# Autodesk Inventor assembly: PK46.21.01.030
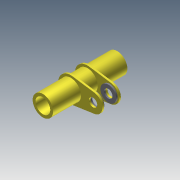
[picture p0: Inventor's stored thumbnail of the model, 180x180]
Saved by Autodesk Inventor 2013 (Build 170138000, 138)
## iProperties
Created: 2005-04
Part Number: PK46.21.01.030
Document SubType Name: Assembly
Designer: salex
Manufacturer: Standard
Standards Organization: Custom
Author: salex
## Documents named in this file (4)
- C:\Product Design Suite 2013\Data\Assy, Chassis, Front\PK46.21.01.030.iam
- C:\Product Design Suite 2013\Data\Assy, Chassis, Front\PK46.21.01.006.ipt
- C:\Product Design Suite 2013\Data\Assy, Chassis, Front\PK46.21.01.007.ipt
- C:\Product Design Suite 2013\Data\Assy, Chassis, Front\PK46.25.02.003.ipt
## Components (5 placed, 3 different names)
1. PK46.21.01.006:1 — Insert:1, Mate:1
2. PK46.21.01.007:1 — Insert:1, Insert:2, Insert:3
3. PK46.21.01.007:2 — Insert:2, Mate:1, Insert:4
4. PK46.25.02.003:1 — Insert:3
5. PK46.25.02.003:2 — Insert:4, Mate:2
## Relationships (6: Insert 4, Mate 2)
- Insert:1: PK46.21.01.006:1 ↔ PK46.21.01.007:1
- Insert:2: PK46.21.01.007:1 ↔ PK46.21.01.007:2
- Mate:1: PK46.21.01.006:1 ↔ PK46.21.01.007:2
- Insert:3: PK46.21.01.007:1 ↔ PK46.25.02.003:1
- Insert:4: PK46.21.01.007:2 ↔ PK46.25.02.003:2
- Mate:2: PK46.25.02.003:2
